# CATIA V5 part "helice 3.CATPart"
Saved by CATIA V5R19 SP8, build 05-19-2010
Part number: helice 3
Bounding box of the stored display mesh (mm): x -17.321 to 17.321, y -30 to 195, z -10 to 20
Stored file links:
  G:\EU_thinkMotion\CFAO_2010\MMS_groupe2\MMS_groupe2\A reprendre\splanchenault\Planchenault\helice 3.CATPart
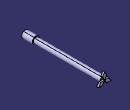
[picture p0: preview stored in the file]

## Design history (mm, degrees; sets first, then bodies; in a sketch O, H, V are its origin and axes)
Body1 (main body)
  Sketch1 on yz-plane, origin (0, 0, 0), H (0, 1, 0), V (0, 0, 1)
    line L1 (-30, 0) -> (0, 0)
    point P1 (-30, 0)
    line L2 (0, 0) -> (190, 0)
    line L3 (190, 0) -> (190, 7.5)
    line L4 (190, 7.5) -> (0, 7.5)
    point P4 (0, 7.5)
    line L5 (0, 7.5) -> (0, 10)
    line L6 (0, 10) -> (-30, 10)
    line L7 (-30, 10) -> (-30, 0)
    length L3 = 7.5
    length L1 = 30
    length L7 = 10
    length L2 = 190
    coincidence: P1 H, P4 V
    horizontal: L1 H, L2 H, L4 H, L6 H
    vertical: L3 V, L5 V, L7 V
  Shaft1: profile Sketch1, axis Sketch1.L2, angle 360
  Sketch2 on face of Shaft1 from Sketch1.L3, origin (0, 190, 0), H (-1, 0, 0), V (0, 0, 1)
    axis line L1 (27.3861, -15.8114) -> (-27.3861, 15.8114)
    line L2 (0, 0) -> (5.7735, 10)
    point P3 (5.7735, 10)
    line L3 (5.7735, 10) -> (0, 20)
    point P4 (0, 20)
    line L4 (0, 20) -> (-5.7735, 10)
    point P5 (-5.7735, 10)
    line L5 (-5.7735, 10) -> (0, 0)
    point P6 (0, 0)
    point P7 (-11.547, 0)
    line L6 (-11.547, 0) -> (0, 0)
    point P8 (-5.7735, -10)
    line L7 (0, 0) -> (-5.7735, -10)
    point P9 (-17.3205, -10)
    line L8 (-5.7735, -10) -> (-17.3205, -10)
    line L9 (-17.3205, -10) -> (-11.547, 0)
    line L10 (17.3205, -10) -> (5.7735, -10)
    point P12 (0, 0)
    line L11 (5.7735, -10) -> (0, 0)
    line L12 (0, 0) -> (11.547, 0)
    line L13 (11.547, 0) -> (17.3205, -10)
    coincidence: L1 O, O P6, O P12, P6 P12
    perpendicularity: L2 L1
    parallelism: L4 L2, L5 L3
    symmetry: O P6 L1, P5 P7 L1, L5 L6 L1, P3 P8 L1, L2 L7 L1, P4 P9 L1, L3 L8 L1, L4 L9 L1
  Pad1: profile Sketch2, direction (0, 1, 0), length 5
